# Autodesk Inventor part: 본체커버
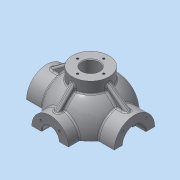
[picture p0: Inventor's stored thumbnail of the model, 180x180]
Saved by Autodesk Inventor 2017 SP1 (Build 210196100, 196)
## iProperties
Created: 2015-12
Part Number: 본체커버
Material: 알루미늄 6061
Document SubType Name: Modeling
Designer: mduedu
Density: 2.71 g/cm^3
Mass: 589.734 g
Surface Area: 460.056 cm^2
Volume: 217.614 cm^3
Appearance: 알루미늄 - 평지
Author: mduedu
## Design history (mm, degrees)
sketch "스케치1"
  geometry: L1 (-53, 0)-(53, 0); A1 r 53 centre (0, 0) between (53, 0) and (-53, 0); 2 further points
  constraints: 2 coincident, 2 end point, 2 point on circle, 1 centre point, 1 horizontal, 1 midpoint
  dimensions: "d0" = 53 radius of A1
revolve "회전1" sketch "스케치1" stored, may be unused: angle "d2" = 90 deg
feature "쉘1" dims "d11" = 10
node "작업 평면1"
sketch "스케치2"
  geometry: C1 r 31 at (0, 0); 1 further point
  constraints: 1 centre point, 1 coincident
  dimensions: "d4" = 62 diameter of C1
extrude "돌출1" join sketch "스케치2" stored distance "d5" = 10; taper "d6" = 0 deg
node "작업 평면2"
sketch "스케치3"
  geometry: C1 r 28 at (0, 0); 1 further point
  constraints: 1 centre point, 1 coincident
  dimensions: "d8" = 56 diameter of C1
extrude "돌출2" join sketch "스케치3" stored distance "d9" = 10; taper "d10" = 0 deg
hole "구멍1" diameter "d14" = 35; stored, may be unused: countersink angle "d18" = 90 deg, drill point angle "d20" = 0 deg; dims "d12" = 10, "d13" = 10, "d15" = 6, "d16" = 4, "d17" = 2, "d19" = 16
hole "구멍2" diameter "d23" = 27; stored, may be unused: countersink angle "d27" = 90 deg, drill point angle "d29" = 0 deg; dims "d21" = 10, "d22" = 10, "d24" = 6, "d25" = 4, "d26" = 2, "d28" = 16
fillet "모깎기1" dims "d30" = 0.3
hole "구멍3" diameter "d33" = 26; stored, may be unused: countersink angle "d37" = 90 deg, drill point angle "d39" = 0 deg; dims "d31" = 10, "d32" = 10, "d34" = 6, "d35" = 4, "d36" = 2, "d38" = 16
chamfer "모따기1" distance "d40" = 1; stored, may be unused: second distance "d41" = 2, angle "d42" = 45 deg
sketch "스케치4"
  geometry: L1 (0, 0)-(0, -25); L2 (0, 0)-(-17.678, -17.678); A1 r 25 centre (0, 0) between (-17.678, -17.678) and (0, -25); 1 further point
  constraints: 4 end point, 2 point on circle, 1 centre point, 1 coincident, 1 vertical
  dimensions: "d43" = 50 diameter of A1; "d47" = 45 deg angle of L1 L2
hole "구멍4" sketch "스케치4" at (-17.678, -17.678) diameter "d49" = 3.242; stored, may be unused: countersink angle "d53" = 90 deg, drill point angle "d55" = 118 deg; dims "d50" = 11, "d51" = 4, "d52" = 2, "d54" = 13
sketch "스케치5"
  geometry: L1 (0, 0)-(0, -20); L2 (0, 0)-(-14.142, -14.142); A1 r 20 centre (0, 0) between (0, -20) and (-14.142, -14.142); 2 further points
  constraints: 4 end point, 2 coincident, 2 point on circle, 1 centre point, 1 vertical
  dimensions: "d59" = 40 diameter of A1; "d65" = 45 deg angle of L1 L2
hole "구멍5" sketch "스케치5" at (-14.142, -14.142) diameter "d67" = 3.242; stored, may be unused: countersink angle "d71" = 90 deg, drill point angle "d73" = 118 deg; dims "d68" = 8, "d69" = 4, "d70" = 2, "d72" = 10
node "작업 평면3"
sketch "스케치6"
  geometry: C1 r 65 at (0, 0); 1 further point
  constraints: 1 centre point, 1 coincident
  dimensions: "d78" = 130 diameter of C1
extrude "돌출3" join sketch "스케치6" distance "d80" = 10; taper "d81" = 0 deg
sketch "스케치7"
  geometry: C1 r 20 at (0, 0); 1 further point
  constraints: 1 centre point, 1 coincident
  dimensions: "d82" = 40 diameter of C1
extrude "돌출4" join sketch "스케치7" stored distance "d84" = 10; taper "d85" = 0 deg
sketch "스케치8"
  geometry: 2 further points
  constraints: 1 coincident
hole "구멍6" sketch "스케치8" at (0, 0) diameter "d86" = 20; stored, may be unused: countersink angle "d90" = 90 deg, drill point angle "d92" = 118 deg; dims "d87" = 7, "d88" = 40, "d89" = 5, "d91" = 10
fillet "모깎기2" dims "d93" = 0.3
sketch "스케치9"
  geometry: L1 (65, -75)-(-65, -75) reference; L2 (-45, -75)-(-38.245, -36.692); A1 r 53 centre (0, 0) between (42.988, 31) and (42.988, -31) reference; 1 further point
  constraints: 2 end point, 1 point on circle, 1 point on line
  dimensions: "d94" = 45 horizontal distance of L2.start point (0, 0); "d95" = 80 deg angle of L2 L1
feature "리브1" sketch "스케치9" dims "d96" = 1, "d97" = 8, "d98" = 0, "d99" = 0, "d100" = 1, "d101" = 1
sketch "스케치10"
  geometry: L1 (0, 0)-(0, -55); L2 (0, 0)-(-38.891, -38.891); A1 r 55 centre (0, 0) between (0, -55) and (-38.891, -38.891); 2 further points
  constraints: 4 end point, 2 coincident, 2 point on circle, 1 centre point, 1 vertical
  dimensions: "d105" = 110 diameter of A1; "d107" = 45 deg angle of L1 L2
hole "구멍7" sketch "스케치10" at (-38.891, -38.891) diameter "d109" = 10; stored, may be unused: countersink angle "d113" = 90 deg, drill point angle "d115" = 118 deg; dims "d110" = 7, "d111" = 40, "d112" = 5, "d114" = 10
fillet "모깎기3" dims "d120" = 3
fillet "모깎기4" dims "d121" = 3, "d122" = 3
fillet "모깎기5" dims "d123" = 3
fillet "모깎기6" dims "d124" = 3
sketch "스케치11"
  geometry: C1 r 5 at (-38.891, 38.891) reference; C2 r 5 at (38.891, 38.891) reference; C3 r 5 at (38.891, -38.891) reference; C4 r 5 at (-38.891, -38.891) reference; C5 r 20 at (0, 0) reference; C6 r 65 at (0, 0) reference; 1 further point
  constraints: 3 other
feature "엠보싱1" sketch "스케치11" dims "d125" = 0.5, "d126" = 0
sketch "스케치12"
  geometry: L1 (0, 100)-(0, -100); L2 (0, 100)-(-150, 100); L3 (-150, 100)-(-150, -100); L4 (-150, -100)-(0, -100); 2 further points
  constraints: 8 end point, 3 perpendicular, 1 coincident, 1 midpoint, 1 vertical
  dimensions: "d127" = 200 distance of L2.end L3.end; "d129" = 150 distance of L3.end L1.end
extrude "돌출5" cut sketch "스케치12" stored distance "d130" = 10; taper "d131" = 0 deg
sketch "스케치13"
  geometry: C1 r 7 at (0, -53); A1 r 53 centre (0, 0) between (-42.113, -32.179) and (42.113, -32.179) reference; 1 further point
  constraints: 1 centre point, 1 point on circle
  dimensions: "d132" = 14 diameter of C1
extrude "돌출6" join sketch "스케치13" distance "d133" = 5; taper "d134" = 0 deg
sketch "스케치14"
  geometry: C1 r 7 at (0, 0) reference; 1 further point
extrude "돌출7" cut sketch "스케치14" stored distance "d135" = 5; taper "d136" = 0 deg
sketch "스케치15"
  geometry: C1 r 2.25 at (0, 53); A1 r 7 centre (0, 53) between (6.965, 52.302) and (-6.965, 52.302) reference; 1 further point
  constraints: 1 centre point, 1 coincident
  dimensions: "d139" = 4.5 diameter of C1
extrude "돌출8" cut sketch "스케치15" stored distance "d141" = 5; taper "d142" = 0 deg
fillet "모깎기7" dims "d143" = 3
fillet "모깎기8" dims "d144" = 1
fillet "모깎기9" dims "d145" = 1
fillet "모깎기10" dims "d146" = 1
node "작업 평면4"
sketch "스케치16"
  geometry: C1 r 28 at (0, 0); 1 further point
  constraints: 1 centre point, 1 coincident
  dimensions: "d148" = 56 diameter of C1
extrude "돌출9" join sketch "스케치16" stored distance "d150" = 5; taper "d151" = 0 deg
hole "구멍8" diameter "d154" = 26; stored, may be unused: countersink angle "d158" = 90 deg, drill point angle "d160" = 118 deg; dims "d152" = 10, "d153" = 10, "d155" = 6, "d156" = 4, "d157" = 2, "d159" = 8
sketch "스케치17" dims "d161" = 40
  geometry: 3 further points
  constraints: 2 vertical alignment, 1 coincident, 2 other
hole "구멍9" sketch "스케치17" at (0, 20) diameter "d163" = 3.242; stored, may be unused: countersink angle "d167" = 90 deg, drill point angle "d169" = 118 deg; dims "d164" = 8, "d165" = 4, "d166" = 2, "d168" = 10
fillet "모깎기11" dims "d173" = 3
chamfer "모따기2" distance "d174" = 1; stored, may be unused: second distance "d175" = 2, angle "d176" = 45 deg
sketch "스케치18"
  geometry: L1 (28, 62)-(28, 46.637) reference; L2 (67, 31)-(44.497, 31) reference; L3 (28, 55)-(60, 31); L4 (-28, 62)-(28, 62) reference; L5 (67, 31)-(67, 0) reference; 1 further point
  constraints: 2 end point, 2 point on line
  dimensions: "d177" = 7 distance from line of L3.start L4; "d178" = 7 distance from line of L3.end L5
feature "리브2" sketch "스케치18" dims "d179" = 1, "d180" = 8, "d181" = 0, "d182" = 0, "d183" = 1, "d184" = 1
fillet "모깎기12" dims "d185" = 3
fillet "모깎기13" dims "d186" = 3
sketch "스케치19"
  geometry: L1 (62, 28)-(46.637, 28) reference; L2 (28, 62)-(28, 46.637) reference; L3 (55, 28)-(28, 55); L4 (0, 62)-(28, 62) reference; L5 (62, 28)-(62, -28) reference; 1 further point
  constraints: 2 end point, 2 point on line
  dimensions: "d187" = 7 distance from line of L3.end L4; "d188" = 7 distance from line of L3.start L5
feature "리브3" sketch "스케치19" dims "d189" = 1, "d190" = 8, "d191" = 0, "d192" = 0, "d193" = 1, "d194" = 1
fillet "모깎기14" dims "d195" = 3
fillet "모깎기15" dims "d196" = 3
node "솔리드1"
mirror "대칭1"
mirror "대칭2"
pattern_circular "원형 패턴1" dims angle "d57" = 360 deg
mirror "대칭3"
pattern_circular "원형 패턴2" dims angle "d75" = 360 deg
pattern_circular "원형 패턴3" dims angle "d103" = 360 deg
pattern_circular "원형 패턴4" dims angle "d118" = 360 deg
pattern_circular "원형 패턴5" dims angle "d171" = 360 deg
mirror "대칭4"
node "투영된 루프1"
other parameters: "d3" = 67, "d7" = 62, "d77" = -85, "d147" = 62
